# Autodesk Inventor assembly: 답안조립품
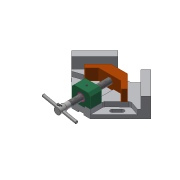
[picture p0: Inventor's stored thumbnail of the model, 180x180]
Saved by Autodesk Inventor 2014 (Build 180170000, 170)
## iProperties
Created: 2019-04
Part Number: 답안조립품
Document SubType Name: Assembly
Designer: 601-25
Author: 601-25
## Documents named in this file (11)
- C:\Users\601-25\Desktop\490408V1002\답안조립품.iam
- C:\Users\601-25\Desktop\490408V1002\리드스크류.ipt
- C:\Users\601-25\Desktop\490408V1002\멈춤나사 M4x5.ipt
- C:\Users\601-25\Desktop\490408V1002\멈춤나사 M4x10.ipt
- C:\Users\601-25\Desktop\490408V1002\베이스.ipt
- C:\Users\601-25\Desktop\490408V1002\볼트 M4x16.ipt
- C:\Users\601-25\Desktop\490408V1002\부시.ipt
- C:\Users\601-25\Desktop\490408V1002\서포트.ipt
- C:\Users\601-25\Desktop\490408V1002\조.ipt
- C:\Users\601-25\Desktop\490408V1002\평행 핀 2.5x24.ipt
- C:\Users\601-25\Desktop\490408V1002\핸들.ipt
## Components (1 placed, 1 different names)
1. 핸들:2 — 각도:4
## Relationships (1: Angle 1)
- 각도:4 [Angle]: 핸들:2
